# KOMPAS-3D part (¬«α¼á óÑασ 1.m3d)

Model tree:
1. Эскиз:1
2. Операция выдавливания:1
     Расстояние 1 = 2; Расстояние 2 = 0.3
3. Эскиз:2
4. Операция выдавливания:2
     Расстояние 1 = 2; Расстояние 2 = 0.3
5. Эскиз:3
6. Операция выдавливания:3
     Расстояние 1 = 2; Расстояние 2 = 0.3
7. Скругление:1
     Радиус = 1; Хорда = 0.2
8. Скругление:2
     Радиус = 0.5; Хорда = 0.2
9. Эскиз:4
10. Вырезать элемент выдавливания:1
     Расстояние 2 = 1; Расстояние 1 = 1.52632
11. Массив по сетке:1  (with: Операция выдавливания:3, Скругление:1, Скругление:2, Вырезать элемент выдавливания:1)  (labels: Экземпляр ( 1, 1 ); Экземпляр ( 2, 1 ); Экземпляр ( 3, 1 ); Экземпляр ( 4, 1 ))
     N 1 = 7; Шаг 1 = 116; Угол раствора = 90; N 2 = 1; Номер 1 = 1; Номер 2 = 1
12. Эскиз:5
13. Вырезать элемент выдавливания:2
     Расстояние 2 = 64; Расстояние 1 = 64
14. Эскиз:6
15. Операция выдавливания:4
     Расстояние 1 = 7.6
16. Эскиз:7
17. Вырезать элемент выдавливания:3
     Расстояние 1 = 97.414
18. Эскиз:8
19. Вырезать элемент выдавливания:4
     Расстояние 1 = 0.5
20. Эскиз:9
21. Вырезать элемент выдавливания:5
     Расстояние 2 = 122.386; Расстояние 1 = 5.61403
22. Эскиз:10
23. Вырезать элемент выдавливания:6
     Расстояние 2 = 6.05758; Расстояние 1 = 2
24. Смещенная плоскость:1
     Расстояние = 2
25. Эскиз:12
26. Операция выдавливания:5
     Расстояние 1 = 0.2
27. Эскиз:13
28. Вырезать элемент выдавливания:8
     Расстояние 2 = 6.05758; Расстояние 1 = 0.5
29. Массив по сетке:2  (with: Вырезать элемент выдавливания:8)  (labels: Экземпляр ( 1, 1 ); Экземпляр ( 2, 1 ); Экземпляр ( 3, 1 ); Экземпляр ( 4, 1 ))
     Наклон = -180; N 1 = 16; Шаг 1 = 2.5; Угол раствора = 90; N 2 = 1; Номер 1 = 1; Номер 2 = 1
30. Эскиз:14
31. Вырезать элемент выдавливания:9
     Расстояние 2 = 6.05758; Расстояние 1 = 0.5
32. Эскиз:15
33. Операция выдавливания:6
     Расстояние 1 = 0.1; Расстояние 2 = 0.2
34. Эскиз:16
35. Операция выдавливания:7
     Расстояние 1 = 43; Расстояние 2 = 0.2
36. Эскиз:17
37. Операция выдавливания:8
     Расстояние 1 = 43; Расстояние 2 = 0.2
38. Эскиз:18
39. Операция выдавливания:9
     Расстояние 1 = 0.3; Расстояние 2 = 0.2
40. Эскиз:19
41. Операция выдавливания:10
     Расстояние 1 = 2; Расстояние 2 = 1
42. Эскиз:20
43. Вырезать элемент выдавливания:10
     Расстояние 2 = 6.05758; Расстояние 1 = 114.508
44. Фаска:1
     Угол = 45.0029; Длина 1 = 1; Длина 2 = 1.0001
45. Скругление:3
     Радиус = 0.5
46. Эскиз:21
47. Операция выдавливания:11
     Расстояние 1 = 0.3; Расстояние 2 = 1
48. Эскиз:22
49. Операция выдавливания:12
     Расстояние 1 = 0.2; Расстояние 2 = 1
50. Эскиз:23
51. Операция выдавливания:13
     Расстояние 1 = 0.8; Расстояние 2 = 1
52. Эскиз:24
53. Операция выдавливания:14
     Расстояние 1 = 0.8; Расстояние 2 = 1
54. Эскиз:25
55. Операция выдавливания:15
     Расстояние 1 = 1.5; Расстояние 2 = 1
56. Эскиз:26
57. Вырезать элемент выдавливания:11
     Расстояние 2 = 6.05758; Расстояние 1 = 11.95
58. Скругление:4
     Радиус = 0.3
59. Скругление:5
     Радиус = 0.5
60. Эскиз:27
61. Операция выдавливания:16
     Расстояние 1 = 0.5; Расстояние 2 = 1
62. Эскиз:28
63. Операция выдавливания:17
     Расстояние 1 = 0.5; Расстояние 2 = 1
64. Эскиз:29
65. Операция выдавливания:18
     Расстояние 1 = 1; Расстояние 2 = 1
66. Эскиз:30
67. Операция выдавливания:19
     Расстояние 1 = 1; Расстояние 2 = 1
68. Эскиз:31
69. Операция выдавливания:20
     Расстояние 1 = 1.5; Расстояние 2 = 1
70. Эскиз:32
71. Вырезать элемент выдавливания:12
     Расстояние 2 = 6.05758; Расстояние 1 = 4
72. Скругление:6
     Радиус = 0.5
73. Скругление:7
     Радиус = 0.5
74. Эскиз:33
75. Операция выдавливания:21
     Расстояние 1 = 1; Расстояние 2 = 1
76. Эскиз:34
77. Операция выдавливания:22
     Расстояние 1 = 0.5; Расстояние 2 = 1

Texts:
  кора верх 1
  Сплав АЛ8  ГОСТ 1583-93
  stalker61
